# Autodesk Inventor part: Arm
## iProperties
Shininess: 77.0
Length Units: 11269
Angle Units: 11279
Time Units: 11290
Mass Units: 11283
Length Display Precision: 3
Angle Display Precision: 2
Created: 2002-01
Part Number: Arm
Document SubType Name: Modeling
Designer: ***
Density: 0.0
Volumn: 0.0
Area: 0.0
PropertySet Name: Model Information
Control State: 0
Master: False
Checked Out: False
Author: ***
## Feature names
1. Extrusion1
2. Extrusion2
